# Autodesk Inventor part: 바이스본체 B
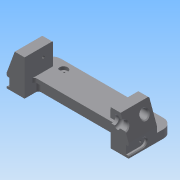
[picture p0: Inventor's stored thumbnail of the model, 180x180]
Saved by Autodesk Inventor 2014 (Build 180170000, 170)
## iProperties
Created: 2017-04
Part Number: 바이스본체 B
Material: 알루미늄 6061
Document SubType Name: Modeling
Designer: mduedu
Density: 2.71 g/cm^3
Appearance: 기본값
Mass: 324.158 g
Surface Area: 275.767 cm^2
Volume: 119.615 cm^3
Author: mduedu
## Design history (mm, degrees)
sketch "스케치1"
  geometry: L1 (-75, 0)-(75, 0); L2 (-75, 0)-(-75, 17); L3 (-53, 17)-(53, 17); L4 (75, 17)-(75, 0); L5 (-75, 17)-(-65.173, 44); L6 (-65.173, 44)-(-53, 44); L7 (-53, 44)-(-53, 17); L8 (0, 0)-(0, 17); L9 (75, 17)-(65.173, 44); L10 (65.173, 44)-(53, 44); L11 (53, 44)-(53, 17); 1 further point
  constraints: 22 end point, 4 perpendicular, 2 horizontal alignment, 2 midpoint, 2 symmetric about line, 1 coincident, 1 collinear, 1 horizontal, 1 vertical
  dimensions: "d0" = 150 distance of L1.start L1.end; "d1" = 17 distance of L1.start L2.end; "d2" = 27 distance of L3.start L6.end; "d3" = 22 distance of L3.start L2.end; "d4" = 70 deg angle of L3 L5; "d54" = 20 deg angle of L9 L4
extrude "돌출1" new body sketch "스케치1" stored distance "d5" = 70; taper "d6" = 0 deg
sketch "스케치2"
  geometry: L1 (0, 70)-(106, 70) reference; L2 (106, 70)-(106, 0) reference; L3 (106, 0)-(0, 0) reference; L4 (0, 47)-(106, 47); L5 (106, 47)-(106, 23); L6 (106, 23)-(0, 23); L7 (0, 23)-(0, 47); L8 (0, 70)-(0, 0) reference; 2 further points
  constraints: 8 end point, 2 parallel, 2 point on line, 1 horizontal, 1 horizontal alignment, 1 midpoint, 1 perpendicular
  dimensions: "d7" = 24 distance between parallel lines of L6 L4
extrude "돌출2" cut sketch "스케치2" stored distance "d9" = 70; taper "d10" = 0 deg
sketch "스케치3"
  geometry: L1 (22, -23)-(128, -23) reference; L2 (128, -47)-(22, -47) reference; L3 (22, -18)-(128, -18); L4 (128, -52)-(22, -52); L5 (22, -18)-(22, -52); L6 (128, -18)-(128, -52); 1 further point
  constraints: 8 end point, 3 parallel, 2 point on line, 1 perpendicular
  dimensions: "d11" = 5 distance between parallel lines of L3 L1; "d12" = 5 distance between parallel lines of L4 L2
extrude "돌출3" cut sketch "스케치3" distance "d13" = 12; taper "d14" = 0 deg
fillet "모깎기1" dims "d15" = 3, "d16" = 3
sketch "스케치4"
  geometry: L1 (103, 23)-(3, 23) reference; L2 (0, 26)-(0, 0) reference; L3 (106, 0)-(0, 0) reference; L4 (106, 26)-(106, 0) reference; L5 (96, 0)-(90, 0); L6 (90, 0)-(90, 19.5); L7 (96, 19.5)-(96, 0); L8 (90, 19.5)-(96, 19.5); A1 r 3 centre (3, 26) between (0, 26) and (3, 23) reference; A2 r 3 centre (103, 26) between (103, 23) and (106, 26) reference; 1 further point
  constraints: 8 end point, 2 perpendicular, 1 horizontal, 1 parallel, 1 point on line
  dimensions: "d17" = 10 distance between parallel lines of L7 L4; "d18" = 6 distance between parallel lines of L7 L6; "d27" = 3.5 distance between parallel lines of L8 L1
extrude "돌출4" join sketch "스케치4" distance "d19" = 12; taper "d20" = 0 deg
chamfer "모따기1" distance "d21" = 3; stored, may be unused: second distance "d22" = 2, angle "d23" = 45 deg
chamfer "모따기2" distance "d24" = 3; stored, may be unused: second distance "d25" = 2, angle "d26" = 45 deg
sketch "스케치5"
  geometry: L1 (-15.5, 35.8)-(-15.5, -25.8) reference; L2 (19.5, 0)-(0, 0) reference; C1 r 6.5 at (9.5, 15); 1 further point
  constraints: 1 centre point
  dimensions: "d28" = 13 diameter of C1; "d30" = 15 distance from line of C1.centre L2; "d31" = 25 distance from line of C1.centre L1
extrude "돌출5" cut sketch "스케치5" stored distance "d32" = 12; taper "d33" = 0 deg
sketch "스케치6"
  geometry: C1 r 5 at (-10, 15); C2 r 5 at (-60, 15); A1 r 6.5 centre (-10, 15) between (-15.766, 12) and (-4.234, 12) reference; A2 r 6.5 centre (-60, 15) between (-65.766, 12) and (-54.234, 12) reference; 1 further point
  constraints: 2 centre point, 2 coincident
  dimensions: "d34" = 10 diameter of C1; "d35" = 10 diameter of C2 (= d34)
extrude "돌출6" cut sketch "스케치6" stored distance "d36" = 12; taper "d37" = 0 deg
chamfer "모따기3" distance "d38" = 1; stored, may be unused: second distance "d39" = 2, angle "d40" = 45 deg
chamfer "모따기4" distance "d41" = 1; stored, may be unused: second distance "d42" = 2, angle "d43" = 45 deg
sketch "스케치7"
  geometry: L1 (-35, 35.8)-(-35, -25.8) reference; L2 (-70, 0)-(0, 0) reference; C1 r 5 at (-35, 15); 1 further point
  constraints: 1 centre point, 1 point on line
  dimensions: "d44" = 10 diameter of C1; "d45" = 15 distance from line of C1.centre L2
extrude "돌출7" cut sketch "스케치7" stored distance "d46" = 12; taper "d47" = 0 deg
chamfer "모따기5" distance "d48" = 1; stored, may be unused: second distance "d49" = 2, angle "d50" = 45 deg
node "작업축1"
sketch "스케치8"
  geometry: L1 (-105, 32)-(105, 32) reference; L2 (58, 32)-(64, 32); L3 (64, 32)-(64, 40); L4 (64, 40)-(58, 40); L5 (58, 40)-(58, 32); L6 (53, 38)-(53, 26) reference; 1 further point
  constraints: 8 end point, 2 parallel, 1 horizontal, 1 perpendicular, 1 point on line
  dimensions: "d51" = 5 distance from line of L6 L2.start; "d52" = 6 distance of L3.end L4.end; "d53" = 16 diameter of L4 L1
revolve "회전1" sketch "스케치8" stored, may be unused: angle "d55" = 90 deg
fillet "모깎기2"
chamfer "모따기6" distance "d56" = 1; stored, may be unused: second distance "d57" = 2, angle "d58" = 45 deg
sketch "스케치9"
  geometry: L1 (17.5, 3)-(52.5, 3); L2 (52.5, 13)-(17.5, 13); L3 (70, 0)-(0, 0) reference; L4 (17.5, 8)-(52.5, 8); A1 r 5 centre (17.5, 8) between (17.5, 13) and (17.5, 3); A2 r 5 centre (52.5, 8) between (52.5, 3) and (52.5, 13); 3 further points
  constraints: 6 end point, 4 point on circle, 3 tangent, 2 centre point, 2 midpoint, 2 parallel, 1 horizontal, 1 vertical alignment
  dimensions: "d59" = 35 distance of L4.start L4.end; "d61" = 5 radius of A2; "d62" = 8 distance between parallel lines of L3 L4
extrude "돌출8" cut sketch "스케치9" distance "d63" = 3; taper "d64" = 0 deg
chamfer "모따기7" distance "d65" = 1; stored, may be unused: second distance "d66" = 2, angle "d67" = 45 deg
chamfer "모따기8" distance "d68" = 1; stored, may be unused: second distance "d69" = 2, angle "d70" = 45 deg
feature "분할1"
sketch "스케치10"
  geometry: A1 r 5 centre (0, 0) between (0, 5) and (0, -5) reference; 1 further point
  constraints: 1 coincident
hole "구멍1" sketch "스케치10" at (0, 0) diameter "d71" = 2.459; stored, may be unused: countersink angle "d75" = 90 deg, drill point angle "d77" = 120 deg; dims "d72" = 4.5, "d73" = 4, "d74" = 2, "d76" = 6
sketch "스케치11"
  geometry: L1 (0, 0)-(0, 27) reference; L2 (0, 27)-(-35, 27) reference; 2 further points
  dimensions: "d78" = 12 distance from line of point (-12, 15.5) L1; "d79" = 11.5 distance from line of point (-12, 15.5) L2
hole "구멍2" sketch "스케치11" at (-12, 15.5) diameter "d80" = 3.242; stored, may be unused: countersink angle "d84" = 90 deg, drill point angle "d86" = 120 deg; dims "d81" = 6, "d82" = 4, "d83" = 2, "d85" = 8
sketch "스케치12"
  geometry: L1 (-75, -35)-(-75, 0) reference; L2 (75, -35)-(75, 0) reference; L3 (75, -35)-(-75, -35); L4 (-75, -35)-(-75, -55); L5 (-75, -55)-(75, -55); L6 (75, -55)-(75, -35); 1 further point
  constraints: 8 end point, 2 parallel, 1 horizontal, 1 perpendicular, 1 point on line
  dimensions: "d87" = 20 distance of L3.end L4.end; "d89" = 150 distance of L4.end L5.end (derived)
extrude "돌출9" join sketch "스케치12" distance "d90" = 10; taper "d91" = 0 deg
sketch "스케치13"
  geometry: L1 (-75, 55)-(-75, 35) reference; L2 (75, 35)-(75, 55) reference; L3 (-75, 45)-(75, 45); 3 further points
  constraints: 2 end point, 2 midpoint, 2 point on line
  dimensions: "d92" = 50 horizontal distance of point (-50, 45) point (0, 0); "d93" = 100 distance of point (50, 45) point (-50, 45)
fillet "모깎기3" dims "d94" = 12
chamfer "모따기9" distance "d95" = 1; stored, may be unused: second distance "d96" = 2, angle "d97" = 45 deg
hole "구멍3" sketch "스케치13" diameter "d98" = 4.134; stored, may be unused: countersink angle "d102" = 90 deg, drill point angle "d104" = 118 deg; dims "d99" = 6, "d100" = 10, "d101" = 4, "d103" = 8
node "솔리드1"
mirror "대칭1"
mirror "대칭2"
mirror "대칭3"
mirror "대칭4"
node "투영된 루프1"
